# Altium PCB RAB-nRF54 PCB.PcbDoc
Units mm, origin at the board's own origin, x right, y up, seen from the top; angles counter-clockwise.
Board outline 50.3 x 82.73 mm, 2 copper layers (Top Layer, Bottom Layer), stack 1.622 mm thick; 96 components, 53 nets, 179 pads, 205 vias.
Unrouted connection lines stored in the file: 13.
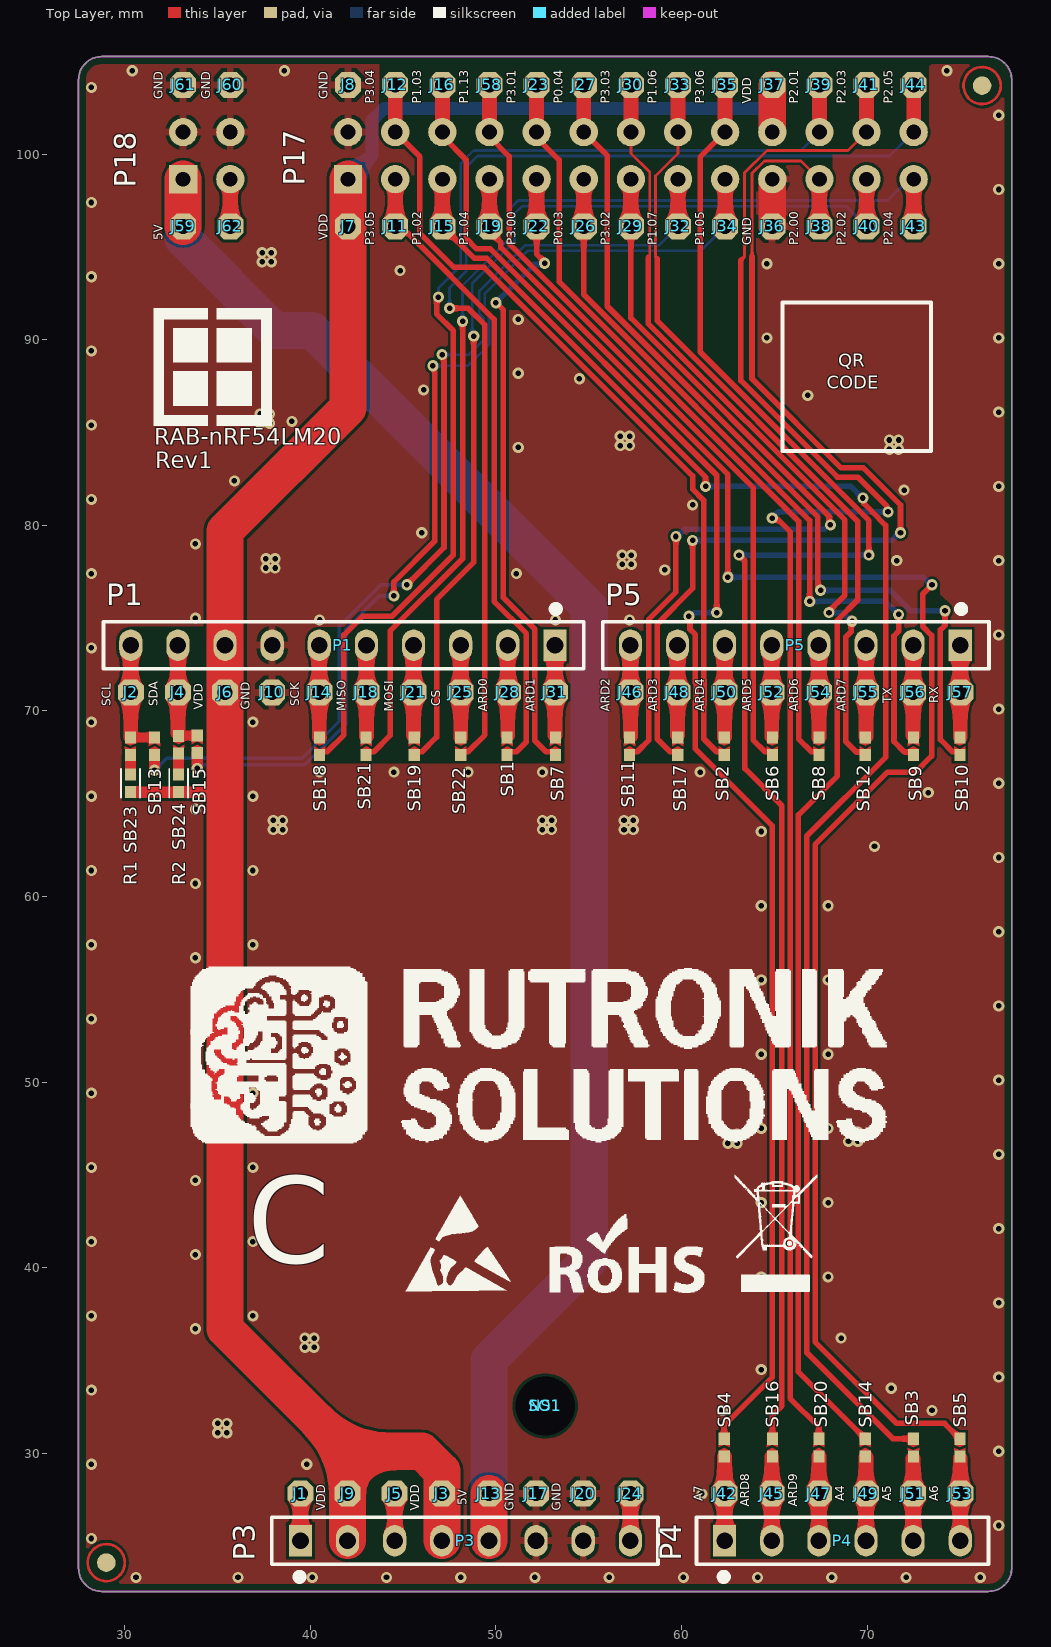
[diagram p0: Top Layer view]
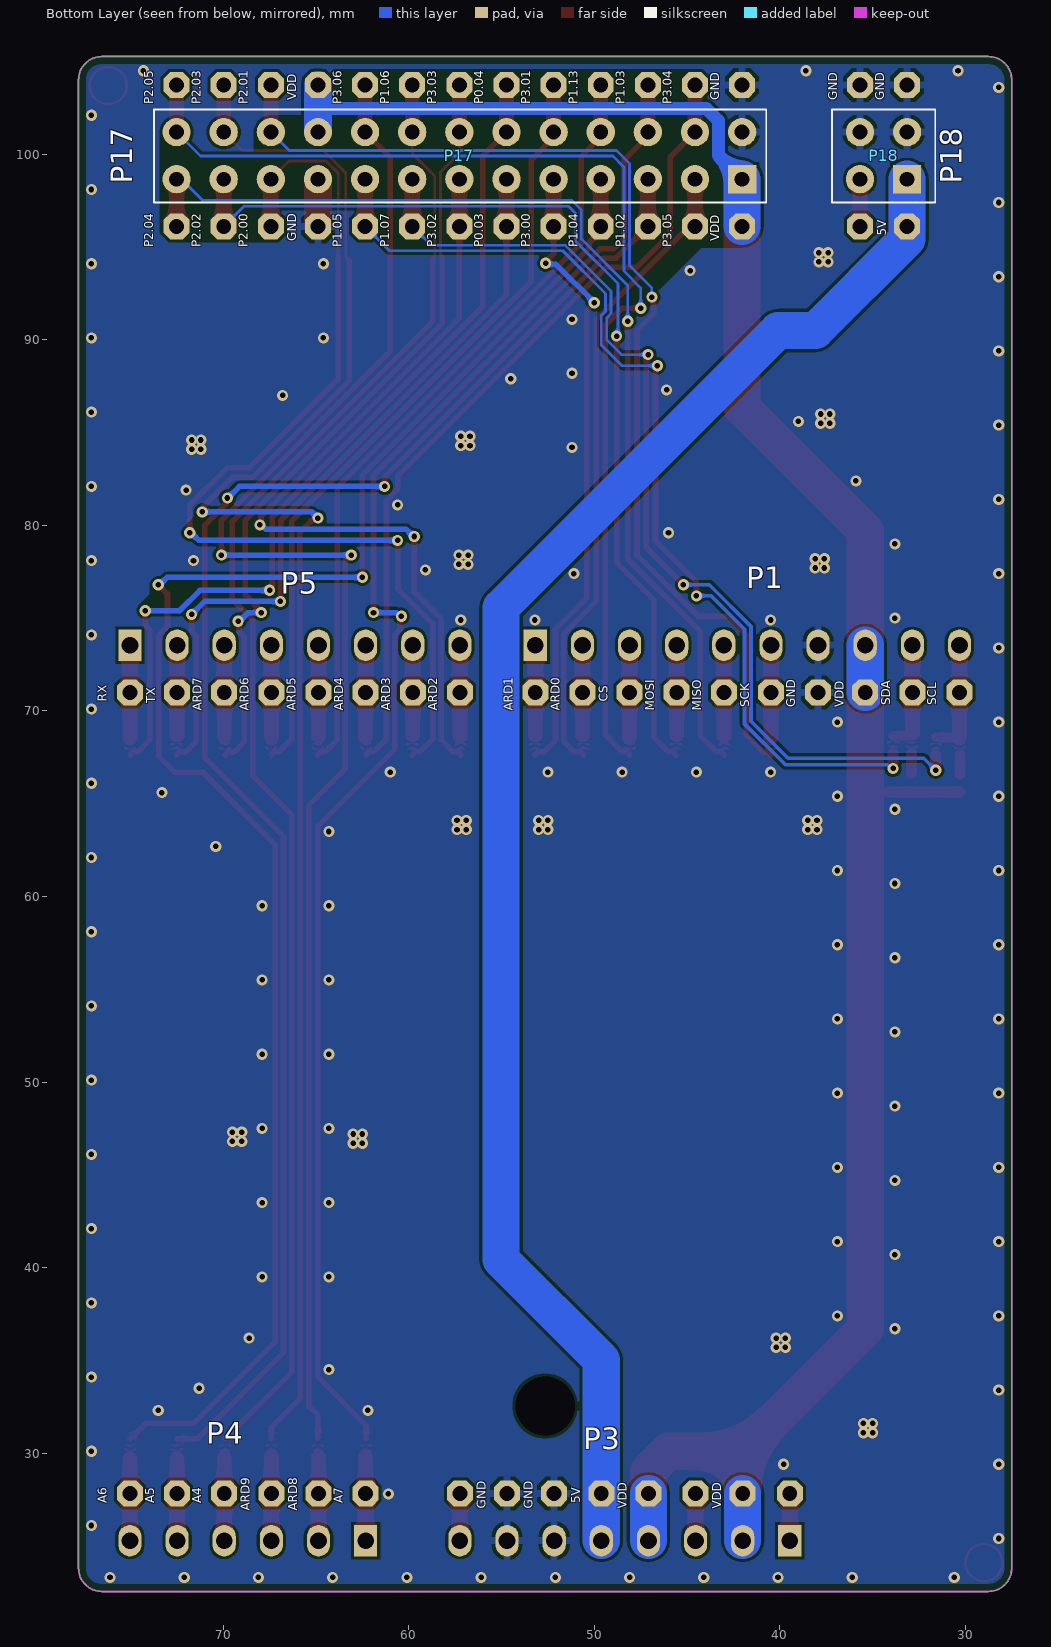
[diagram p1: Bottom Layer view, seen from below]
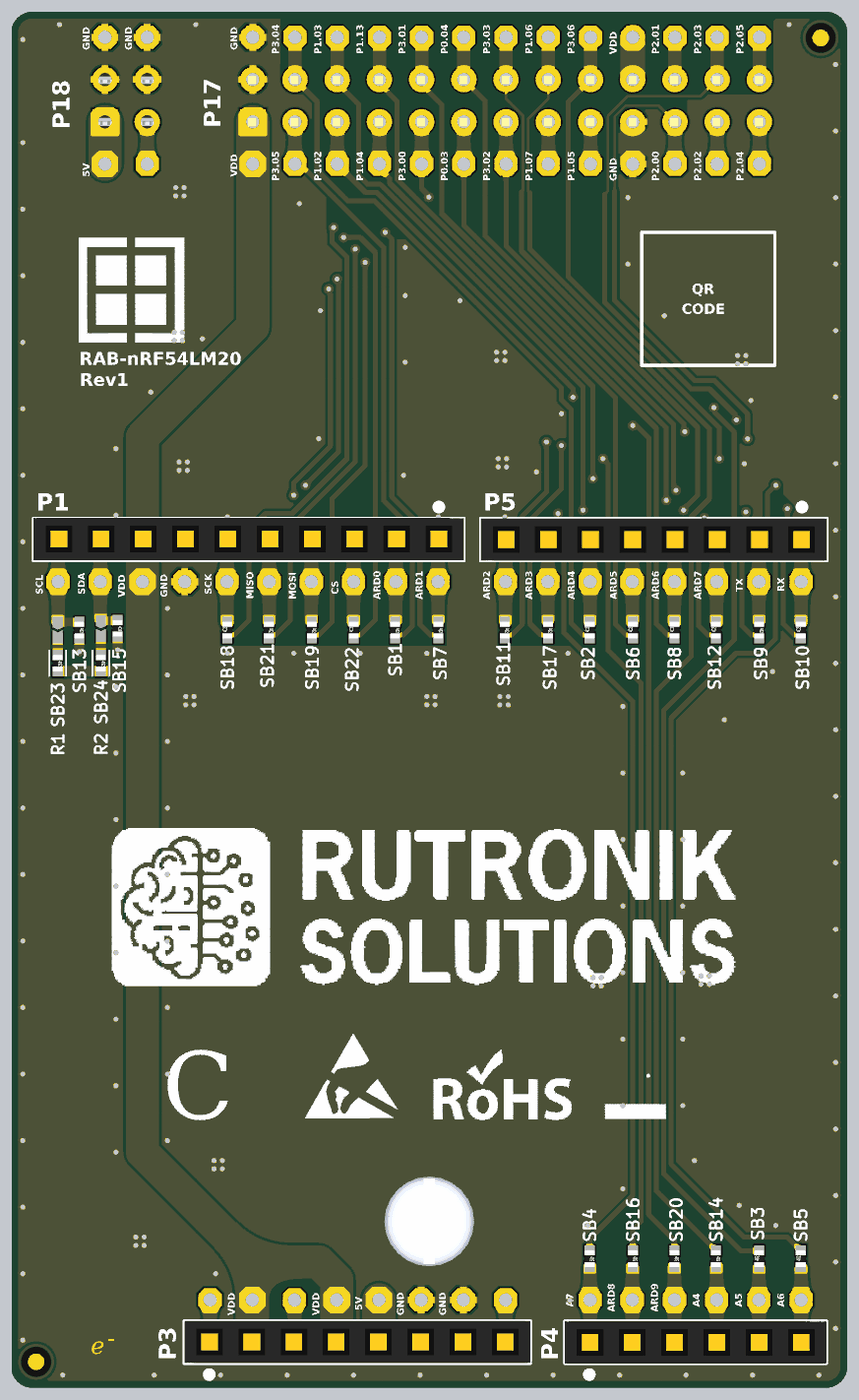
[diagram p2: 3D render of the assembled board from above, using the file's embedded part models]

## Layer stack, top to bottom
Top Solder: solder mask 0.01, Solder Resist, Dk 3.5
Top Layer: signal copper 0.036
Dielectric 1: dielectric 1.55, FR-4, Dk 4.2
Bottom Layer: signal copper 0.036
Bottom Solder: solder mask 0.01, Solder Resist, Dk 3.5

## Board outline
27.5,23.811 27.5,104 cw(c28.77,104) 28.77,105.27 76.53,105.27 cw(c76.53,104) 77.8,104 77.8,23.811 cw(c76.53,23.811) 76.53,22.541 28.77,22.541 cw(c28.77,23.811)

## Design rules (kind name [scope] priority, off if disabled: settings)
BoardOutlineClearance [All] p1: gap=0.4 ignorepadtopadclearanceinfootprint=FALSE
Clearance [All] p1: gap=0.15 ignorepadtopadclearanceinfootprint=FALSE
ComponentClearance "Schematic Component Clearance Constraint_1" [InComponent('NS1')] p1: gap=-1 collisioncheckmode=3 verticalgap=2540 showdistances=FALSE
ComponentClearance "Schematic Component Clearance Constraint" [InComponent('SO1')] p2: gap=-1 collisioncheckmode=3 verticalgap=2540 showdistances=FALSE
ComponentClearance [All] p3: gap=0.254 collisioncheckmode=3 verticalgap=0.254 showdistances=FALSE
HoleSize [All] p1: absolutevalues=TRUE maxlimit=12 minlimit=0.3 maxpercent=80.000 minpercent=20.000
HoleToHoleClearance [All] p1: gap=0.15 allowstackedmicrovias=TRUE
MinimumSolderMaskSliver [All] p1: minsoldermaskwidth=0
PolygonConnect [All] p1: thpad.connectstyle=Relief thpad.reliefconductorwidth=0.4 thpad.reliefentries=4 thpad.polygonreliefangle="90 Angle" thpad.airgapwidth=0.2 smdpad.connectstyle=Relief smdpad.reliefconductorwidth=0.4 smdpad.reliefentries=4 smdpad.polygonreliefangle="90 Angle" smdpad.airgapwidth=0.2 via.connectstyle=Direct via.reliefconductorwidth=0.254 via.reliefentries=4 via.polygonreliefangle="90 Angle" via.airgapwidth=0.254
RoutingVias [All] p1: holewidth=0.3 width=0.6 viastyle="Through Hole" minholewidth=0.3 minwidth=0.6 maxholewidth=0.3 maxwidth=0.6
SilkToSilkClearance [All] p1: silktosilkclearance=0
SilkToSolderMaskClearance [IsPad] p1: minsilkscreentomaskgap=0 clearancetoexposedcopper=TRUE
SolderMaskExpansion [All] p1: expansion=0.102 istentingtop=FALSE
SupplyNets "Schematic Supply Nets_4" [InNet('5V')] p1: voltage=0.000
SupplyNets "Schematic Supply Nets_2" [InNet('GND')] p2: voltage=0.000
SupplyNets "Schematic Supply Nets" [InNet('VDDIO')] p3: voltage=0.000
Width [All] p1: maxlimit=4 minlimit=0.15 preferedwidth=0.25
24 further rules are at their usual default settings.

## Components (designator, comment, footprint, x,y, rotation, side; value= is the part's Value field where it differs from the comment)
J1 "pin_tht" PIN_THT 39.463,27.821 r0 top
J2 "pin_tht" PIN_THT 30.319,71.001 r0 top
J3 "pin_tht" PIN_THT 47.083,27.821 r0 top
J4 "pin_tht" PIN_THT 32.859,71.001 r0 top
J5 "pin_tht" PIN_THT 44.543,27.821 r0 top
J6 "pin_tht" PIN_THT 35.399,71.001 r0 top
J7 "pin_tht" PIN_THT 42.032,96.114 r0 top
J8 "pin_tht" PIN_THT 42.032,103.734 r0 top
J9 "pin_tht" PIN_THT 42.003,27.821 r0 top
J10 "pin_tht" PIN_THT 37.939,71.001 r90 top
J11 "pin_tht" PIN_THT 44.572,96.114 r0 top
J12 "pin_tht" PIN_THT 44.572,103.734 r90 top
J13 "pin_tht" PIN_THT 49.623,27.821 r90 top
J14 "pin_tht" PIN_THT 40.479,71.001 r90 top
J15 "pin_tht" PIN_THT 47.112,96.114 r90 top
J16 "pin_tht" PIN_THT 47.112,103.734 r90 top
J17 "pin_tht" PIN_THT 52.163,27.821 r90 top
J18 "pin_tht" PIN_THT 43.019,71.001 r90 top
J19 "pin_tht" PIN_THT 49.652,96.114 r90 top
J20 "pin_tht" PIN_THT 54.703,27.821 r90 top
J21 "pin_tht" PIN_THT 45.559,71.001 r0 top
J22 "pin_tht" PIN_THT 52.192,96.114 r90 top
J23 "pin_tht" PIN_THT 52.192,103.734 r90 top
J24 "pin_tht" PIN_THT 57.243,27.821 r90 top
J25 "pin_tht" PIN_THT 48.099,71.001 r90 top
J26 "pin_tht" PIN_THT 54.732,96.114 r90 top
J27 "pin_tht" PIN_THT 54.732,103.734 r90 top
J28 "pin_tht" PIN_THT 50.639,71.001 r90 top
J29 "pin_tht" PIN_THT 57.272,96.114 r90 top
J30 "pin_tht" PIN_THT 57.272,103.734 r90 top
J31 "pin_tht" PIN_THT 53.179,71.001 r0 top
J32 "pin_tht" PIN_THT 59.812,96.114 r90 top
J33 "pin_tht" PIN_THT 59.812,103.734 r90 top
J34 "pin_tht" PIN_THT 62.352,96.114 r90 top
J35 "pin_tht" PIN_THT 62.352,103.734 r90 top
J36 "pin_tht" PIN_THT 64.892,96.114 r90 top
J37 "pin_tht" PIN_THT 64.892,103.734 r90 top
J38 "pin_tht" PIN_THT 67.432,96.114 r90 top
J39 "pin_tht" PIN_THT 67.432,103.734 r90 top
J40 "pin_tht" PIN_THT 69.972,96.114 r90 top
J41 "pin_tht" PIN_THT 69.972,103.734 r0 top
J42 "pin_tht" PIN_THT 62.323,27.821 r90 top
J43 "pin_tht" PIN_THT 72.512,96.114 r90 top
J44 "pin_tht" PIN_THT 72.512,103.734 r90 top
J45 "pin_tht" PIN_THT 64.863,27.821 r90 top
J46 "pin_tht" PIN_THT 57.243,71.001 r90 top
J47 "pin_tht" PIN_THT 67.403,27.821 r90 top
J48 "pin_tht" PIN_THT 59.783,71.001 r90 top
J49 "pin_tht" PIN_THT 69.943,27.821 r90 top
J50 "pin_tht" PIN_THT 62.323,71.001 r90 top
J51 "pin_tht" PIN_THT 72.483,27.821 r0 top
J52 "pin_tht" PIN_THT 64.863,71.001 r90 top
J53 "pin_tht" PIN_THT 75.023,27.821 r90 top
J54 "pin_tht" PIN_THT 67.403,71.001 r90 top
J55 "pin_tht" PIN_THT 69.943,71.001 r90 top
J56 "pin_tht" PIN_THT 72.483,71.001 r90 top
J57 "pin_tht" PIN_THT 75.023,71.001 r90 top
J58 "pin_tht" PIN_THT 49.652,103.734 r90 top
J59 "pin_tht" PIN_THT 33.142,96.114 r90 top
J60 "pin_tht" PIN_THT 35.682,103.734 r90 top
J61 "pin_tht" PIN_THT 33.142,103.734 r0 top
J62 "pin_tht" PIN_THT 35.682,96.114 r0 top
NS1 "NYLON_SCREW" 29311 52.65,32.541 r0 top value=P/N29341
P1 "DIGITAL 1" Arduino_HDR1X10_main 53.179,73.541 r180 top value=75915-310LF
P3 "POWER" rduino_HDR1X8_main 39.463,25.281 r0 top value=75915-308LF
P4 "ANALOG IN" Arduino_HDR1X6_main 62.323,25.281 r0 top value=75915-306LF
P5 "DIGITAL 2" rduino_HDR1X8_main 75.023,73.541 r180 top value=75915-308LF
P17 "Header 13X2" RECEPTACLE_2x13_2.54_5x8.5 42.032,101.194 r0 bottom value=87606-313LF
P18 "Header 2X2H" RECEPTACLE_2x2_2.54_5x8.5 33.142,101.194 r0 bottom value=87606-302LF
R1 "Res2" R0402 30.3,66.1 r270 top value=10K
R2 "Res2" R0402 32.9,66.1 r270 top value=10K
SB1 "Closed" SB_0402 50.6,68.1 r270 top value=0R
SB2 "Closed" SB_0402 62.3,68.1 r90 top value=0R
SB3 "Closed" SB_0402 72.5,30.3 r90 top value=0R
SB4 "Closed" SB_0402 62.3,30.3 r270 top value=0R
SB5 "Closed" SB_0402 75,30.3 r90 top value=0R
SB6 "Closed" SB_0402 64.9,68.1 r90 top value=0R
SB7 "Closed" SB_0402 53.2,68.1 r270 top value=0R
SB8 "Closed" SB_0402 67.4,68.1 r90 top value=0R
SB9 "Closed" SB_0402 72.5,68.1 r270 top value=0R
SB10 "Closed" SB_0402 75,68.1 r90 top value=0R
SB11 "Closed" SB_0402 57.2,68.1 r270 top value=0R
SB12 "Closed" SB_0402 69.9,68.1 r90 top value=0R
SB13 "Closed" SB_0402 31.6,68.1 r270 top value=0R
SB14 "Closed" SB_0402 69.9,30.3 r270 top value=0R
SB15 "Closed" SB_0402 33.9,68.2 r270 top value=0R
SB16 "Closed" SB_0402 64.9,30.3 r270 top value=0R
SB17 "Closed" SB_0402 59.8,68.1 r270 top value=0R
SB18 "Closed" SB_0402 40.5,68.1 r90 top value=0R
SB19 "Closed" SB_0402 45.6,68.1 r270 top value=0R
SB20 "Closed" SB_0402 67.4,30.3 r270 top value=0R
SB21 "Closed" SB_0402 43,68.1 r270 top value=0R
SB22 "Closed" SB_0402 48.1,68.1 r90 top value=0R
SB23 "Opened" "SB_0402 - open" 30.3,68.1 r90 top value=0R
SB24 "Opened" "SB_0402 - open" 32.9,68.175 r90 top value=0R
SO1 "STANDOFF" 24475 52.65,32.541 r0 top value=P/N25512

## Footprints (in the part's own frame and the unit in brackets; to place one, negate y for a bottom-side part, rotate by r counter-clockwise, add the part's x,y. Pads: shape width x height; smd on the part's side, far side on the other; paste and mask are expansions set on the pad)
24475 [mm] "5mm Hex Female Standoff P/N 24475"
  body extent -2.89,-2.5 2.89,2.5
29311 [mm] "M3 Pan Head screw, 6.0 L P/N 29311"
  body extent -2.7,-2.7 2.7,2.7, height 1.75
Arduino_HDR1X6_main [mm]
  rect 1.25x1.7 hole 0.9: 1(0,0)
  oval 1.25x1.7 hole 0.9: 2(2.54,0) 3(5.08,0) 4(7.62,0) 5(10.16,0) 6(12.7,0)
  silkscreen extent -1.51,-1.27 14.22,1.27, body extent -1.52,-1.27 14.22,1.27, height 8.6
Arduino_HDR1X10_main [mm]
  rect 1.25x1.7 hole 0.9: 1(0,0)
  oval 1.25x1.7 hole 0.9: 2(2.54,0) 3(5.08,0) 4(7.62,0) 5(10.16,0) 6(12.7,0) 7(15.24,0) 8(17.78,0) 9(20.32,0) 10(22.86,0)
  silkscreen extent -1.55,-1.27 24.33,1.27, body extent -1.57,-1.29 24.33,1.25, height 8.6
PIN_THT [mm]
  oct 1.4x1.4 hole 0.8: 1(0,0)
R0402 [mm]
  rect 0.65x0.6 smd: 1(-0.475,0) 2(0.475,0)
  silkscreen extent -0.76,-0.51 0.76,0.51, body extent -0.5,-0.3 0.5,0.3, height 0.2
rduino_HDR1X8_main [mm]
  rect 1.25x1.7 hole 0.9: 1(0,0)
  oval 1.25x1.7 hole 0.9: 2(2.54,0) 3(5.08,0) 4(7.62,0) 5(10.16,0) 6(12.7,0) 7(15.24,0) 8(17.78,0)
  silkscreen extent -1.55,-1.27 19.27,1.27, body extent -1.55,-1.26 19.27,1.28, height 8.6
RECEPTACLE_2x2_2.54_5x8.5 [mil]
  rect 60x60 hole 31.5: 1(0,100)
  round 60 hole 31.5: 2(0,0) 3(100,100) 4(100,0)
  silkscreen extent -60,-48 159,150, body extent -60,-48 160,149, height 335
RECEPTACLE_2x13_2.54_5x8.5 [mil]
  rect 60x60 hole 31.5: 1(0,100)
  round 60 hole 31.5: 2(0,0) 3(100,100) 4(100,0) 5(200,100) 6(200,0) 7(300,100) 8(300,0) 9(400,100) 10(400,0) 11(500,100) 12(500,0) 13(600,100) 14(600,0) 15(700,100) 16(700,0) 17(800,100) 18(800,0) 19(900,100) 20(900,0) 21(1000,100) 22(1000,0) 23(1100,100) 24(1100,0) 25(1200,100) 26(1200,0)
  silkscreen extent -51,-48 1248,150, body extent -51,-49 1249,151, height 331
SB_0402 [mm]
  rect 0.65x0.6 smd: 1(-0.475,0) 2(0.475,0)
  Top Layer region: -0.008,-0.3 -0.157,-0.3 -0.157,0.3 -0.008,0.3 -0.155,0
  Top Layer region: 0.164,-0.3 0.162,-0.3 0.015,0 0.162,0.3 0.164,0.3
  body extent -0.5,-0.3 0.5,0.3, height 0.2
"SB_0402 - open" [mm]
  rect 0.65x0.6 smd: 1(-0.475,0) 2(0.475,0)
  Top Layer region: -0.003,-0.3 -0.152,-0.3 -0.152,0.3 -0.003,0.3 -0.15,0
  Top Layer region: 0.169,-0.3 0.167,-0.3 0.02,0 0.167,0.3 0.169,0.3

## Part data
J1 J2 J3 J4 J5 J6 J7 J8 J9 J10 J11 J12 J13 J14 J15 J16 J17 J18 J19 J20 J21 J22 J23 J24 J25 J26 J27 J28 J29 J30 J31 J32 J33 J34 J35 J36 J37 J38 J39 J40 J41 J42 J43 J44 J45 J46 J47 J48 J49 J50 J51 J52 J53 J54 J55 J56 J57 J58 J59 J60 J61 J62: "Through-hole pin for wire connection."
NS1: "M3 Pan Head Machine Screw, 6.00L P/N 29341", Manufacturer="Keystone Electronics", Manufacturer Part No.="P/N 29341", Supplier part number=BAT4868
P1: library part "Header 10", Manufacturer="Amphenol ICC", Manufacturer Part No.=75915-310LF, Supplier part number=CONN7354
P3 P5: library part "Header 8", Manufacturer="Amphenol ICC", Manufacturer Part No.=75915-308LF, Supplier part number=CONN8727
P4: library part "Header 6", Manufacturer="Amphenol ICC", Manufacturer Part No.=75915-306LF, Supplier part number=CONN8726
P17: "Header, 13-Pin, Dual row", Manufacturer="Amphenol ICC", Manufacturer Part No.=87606-313LF, Supplier part number=CONN11183
P18: "Header, 2-Pin, Dual row, Right Angle", Manufacturer="Amphenol ICC", Manufacturer Part No.=87606-302LF, Supplier part number=CONN9239
R1 R2: Manufacturer=Yageo, Manufacturer Part No.=RC0402JR-1310KL, Supplier part number=WRC51147
SB1 SB2 SB3 SB4 SB5 SB6 SB7 SB8 SB9 SB10 SB11 SB12 SB13 SB14 SB15 SB16 SB17 SB18 SB19 SB20 SB21 SB22 SB23 SB24: library part "Circuit Breaker_close", "Circuit Breaker", Manufacturer=Yageo, Manufacturer Part No.=RC0402FR-070RL, Supplier part number=WRC53079
SO1: "5mm Hex Female Standoff P/N 25512", Manufacturer="Keystone Electronics", Manufacturer Part No.="P/N 25512", Supplier part number=BAT6084

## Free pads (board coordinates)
  round 1 smd paste-1 mask+0.4: ""(29,24.1) ""(76.2,103.7)
  round 0 hole 3.2: ""(52.65,32.541)

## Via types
v1: diameter 0.6, hole 0.3, Top Layer to Bottom Layer, tented both sides, 205 vias

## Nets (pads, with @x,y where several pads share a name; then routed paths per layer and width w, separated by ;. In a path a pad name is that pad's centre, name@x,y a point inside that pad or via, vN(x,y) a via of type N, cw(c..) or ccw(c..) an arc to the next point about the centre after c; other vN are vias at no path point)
5V: J13.1 J59.1 P3.5 P18.1 | length 90.9
  Top Layer w2: J59.1 P18.1 ; P3.5 J13.1
  Bottom Layer w2: P18.1 J59.1 33.142,95.436 38.078,90.5 40.1,90.5 55.029,75.571 55.029,40.429 49.623,35.023 J13.1 P3.5
AN_A4: J49.1 P4.4 SB14.2 | length 4.5
  Top Layer w0.8: P4.4 J49.1 SB14.2@69.943,29.782
AN_A5: J51.1 P4.5 SB3.1 | length 4.4
  Top Layer w0.8: P4.5 J51.1 SB3.1@72.483,29.715
AN_A6: J53.1 P4.6 SB5.1 | length 4.4
  Top Layer w0.8: P4.6 J53.1 SB5.1@75.023,29.713
AN_A7: J42.1 P4.1 SB4.2 | length 4.5
  Top Layer w0.8: P4.1 J42.1 SB4.2@62.323,29.802
ARD_IO0: J28.1 P1.2 SB1.1 | length 4.8
  Top Layer w0.8: SB1.1@50.639,68.696 J28.1 P1.2
ARD_IO1: J31.1 P1.1 SB7.1 | length 4.9
  Top Layer w0.8: SB7.1@53.179,68.686 J31.1 P1.1
ARD_IO2: J46.1 P5.8 SB11.1 | length 4.9
  Top Layer w0.8: SB11.1@57.243,68.646 J46.1 P5.8
ARD_IO3: J48.1 P5.7 SB17.1 | length 4.8
  Top Layer w0.8: SB17.1@59.783,68.7 J48.1 P5.7
ARD_IO4: J50.1 P5.6 SB2.2 | length 4.9
  Top Layer w0.8: SB2.2@62.323,68.598 J50.1 P5.6
ARD_IO5: J52.1 P5.5 SB6.2 | length 4.9
  Top Layer w0.8: SB6.2@64.863,68.612 J52.1 P5.5
ARD_IO6: J54.1 P5.4 SB8.2 | length 5
  Top Layer w0.8: SB8.2 67.403,68.578 J54.1 P5.4
ARD_IO7: J55.1 P5.3 SB12.2 | length 4.9
  Top Layer w0.8: SB12.2@69.943,68.618 J55.1 P5.3
ARD_IO8: J45.1 P4.2 SB16.2 | length 4.5
  Top Layer w0.8: P4.2 J45.1 SB16.2@64.863,29.788
ARD_IO9: J47.1 P4.3 SB20.2 | length 4.5
  Top Layer w0.8: SB20.2 67.403,29.822 J47.1 P4.3
GND: J8.1 J10.1 J17.1 J20.1 J36.1 J60.1 J61.1 P1.7 P3.6 P3.7 P17.2 P17.19 P18.2 P18.4 | length 2.7
  Top Layer w0.8: P17.2@42.032,101.043 P17.2
  Top Layer w1.5: J36.1 P17.19
  other v1: 30.6,23.3 36.1,23.3 40.1,23.3 44.1,23.3 48.1,23.3 52.1,23.3 56.1,23.3 60.1,23.3 64.1,23.3 68.1,23.3 72.1,23.3 76.1,23.3 28.2,25.4 77.1,26.1 61.1,27.8 28.2,29.4 39.8,29.4 77.1,30.1 35,31.1 35.5,31.1 35,31.6 35.5,31.6 62.2,32.3 73.5,32.3 28.2,33.4 71.3,33.5 77.1,34.1 64.3,34.5 39.7,35.7 40.2,35.7 39.7,36.2 40.2,36.2 68.6,36.2 33.8,36.7 28.2,37.4 36.9,37.4 77.1,38.1 64.3,39.5 67.9,39.5 33.8,40.7 28.2,41.4 36.9,41.4 77.1,42.1 64.3,43.5 67.9,43.5 33.8,44.7 28.2,45.4 36.9,45.4 77.1,46.1 62.5,46.7 63,46.7 69,46.8 69.5,46.8 62.5,47.2 63,47.2 69,47.3 69.5,47.3 64.3,47.5 67.9,47.5 33.8,48.7 28.2,49.4 36.9,49.4 77.1,50.1 64.3,51.5 67.9,51.5 33.8,52.7 28.2,53.4 36.9,53.4 77.1,54.1 64.3,55.5 67.9,55.5 33.8,56.7 28.2,57.4 36.9,57.4 77.1,58.1 64.3,59.5 67.9,59.5 33.8,60.7 28.2,61.4 36.9,61.4 77.1,62.1 70.4,62.7 64.3,63.5 38,63.6 38.5,63.6 52.5,63.6 53,63.6 56.9,63.6 57.4,63.6 38,64.1 38.5,64.1 52.5,64.1 53,64.1 56.9,64.1 57.4,64.1 33.8,64.7 28.2,65.4 36.9,65.4 73.3,65.6 77.1,66.1 40.5,66.7 44.5,66.7 48.5,66.7 52.5,66.7 61,66.7 28.2,69.4 36.9,69.4 77.1,70.1 28.2,73.4 77.1,74.1 40.5,74.9 53.2,74.9 57.2,74.9 33.8,75 28.2,77.4 51.1,77.4 59.1,77.6 37.6,77.7 38.1,77.7 56.8,77.9 57.3,77.9 71.6,78.1 77.1,78.1 37.6,78.2 38.1,78.2 56.8,78.4 57.3,78.4 33.8,79 46,79.6 60.6,81.1 28.2,81.4 72,81.9 77.1,82.1 35.9,82.4 71.2,84.1 71.7,84.1 51.2,84.2 56.7,84.3 57.2,84.3 71.2,84.6 71.7,84.6 56.7,84.8 57.2,84.8 28.2,85.4 37.3,85.5 37.8,85.5 39,85.6 37.3,86 37.8,86 77.1,86.1 66.8,87 46.1,87.3 54.5,87.9 51.2,88.2 28.2,89.4 64.6,90.1 77.1,90.1 51.2,91.1 28.2,93.4 44.838,93.732 64.6,94.1 77.1,94.1 37.4,94.2 37.9,94.2 37.4,94.7 37.9,94.7 28.2,97.4 77.1,98.1 77.1,102.1 28.2,103.6 30.4,104.5 38.6,104.5 74.3,104.5
I2C_SCL: J2.1 P1.10 SB13.1 SB23.2 | length 6.2
  Top Layer w0.5: SB23.2 SB13.1
  Top Layer w0.8: SB23.2@30.319,68.594 J2.1 P1.10
I2C_SDA: J4.1 P1.9 SB15.1 SB24.2 | length 5.7
  Top Layer w0.5: SB24.2 32.912,68.662 33.887,68.662 SB15.1
  Top Layer w0.8: SB24.2@32.859,68.816 J4.1 P1.9
NetJ1_1: J1.1 P3.1 | length 2.5
  Top Layer w0.8: P3.1 J1.1
NetJ5_1: J5.1 P3.3 | length 2.5
  Top Layer w0.8: P3.3 J5.1
NetJ24_1: J24.1 P3.8 | length 2.5
  Top Layer w0.8: P3.8 J24.1
NetJ62_1: J62.1 P18.3 | length 2.5
  Top Layer w0.8: J62.1 P18.3
NetR1_1: R1.1 SB23.1 | length 1
  Top Layer w0.6: R1.1@30.3,66.6 SB23.1
NetR2_1: R2.1 SB24.1 | length 1.1
  Top Layer w0.6: R2.1@32.9,66.65 SB24.1
P0.03: J26.1 P17.11 SB9.2 | length 41.2
  Top Layer w0.3: J26.1 54.732,92.441 66.9,80.273 66.9,75.913 v1(66.913,75.9) ; v1(71.7,75.2) 71.7,74.291 71.45,74.041 71.45,68.35 72,67.8 72.35,67.8 72.5,67.65 SB9.2
  Top Layer w0.8: J26.1 P17.11
  Bottom Layer w0.3: v1(66.913,75.9) 71,75.9 v1(71.7,75.2)
P0.04: J27.1 P17.12 SB10.1 | length 48.1
  Top Layer w0.3: P17.12 56,99.926 56,91.809 67.35,80.459 67.35,76.731 67.5,76.581 v1(67.5,76.5) ; v1(74.2,75.4) 74.2,74.617 73.95,74.367 73.95,68.45 74.6,67.8 74.85,67.8 75,67.65 SB10.1
  Top Layer w0.8: P17.12 J27.1
  Bottom Layer w0.3: v1(67.5,76.5) 71.249,76.5 72.349,75.4 v1(74.2,75.4)
P1.02: J15.1 P17.5 SB3.2 | length 87.6
  Top Layer w0.3: J15.1 48.826,94.4 49.5,94.4 61.3,82.6 v1(61.3,82.097) ; v1(69.776,81.476) 69.833,81.418 69.833,81.167 70.286,80.714 71,80 71,67.5 66.75,63.25 66.75,35.414 71.389,30.775 SB3.2
  Top Layer w0.8: J15.1 P17.5
  Bottom Layer w0.3: v1(61.3,82.097) 69.124,82.097 69.746,81.476 v1(69.776,81.476)
P1.03: J16.1 P17.6 SB4.1 | length 83.9
  Top Layer w0.3: P17.6 47.112,100.988 48.4,99.7 48.4,95.463 48.963,94.9 49.7,94.9 61.9,82.7 v1(61.9,75.3) ; v1(60.4,75.1) 60.457,75.043 60.457,74.4 60.75,74.108 60.75,71.509 60.783,71.476 60.783,70.527 60.75,70.494 60.75,67.95 64.9,63.8 64.9,34.1 62.3,31.5 SB4.1
  Top Layer w0.8: P17.6 J16.1
  Bottom Layer w0.3: v1(60.4,75.1) 60.481,75.1 60.681,75.3 v1(61.9,75.3)
P1.04: J19.1 P17.7 SB5.2 | length 92.6
  Top Layer w0.3: J19.1 49.652,95.852 50.264,95.24 50.264,94.972 62.5,82.736 v1(62.5,77.2) ; v1(73.5,76.8) 73,76.3 73,74.558 73.483,74.074 73.483,67.559 72.624,66.7 71.1,66.7 67.2,62.8 67.2,36 71.6,31.6 74.175,31.6 74.825,30.95 74.85,30.95 75,30.8 SB5.2
  Top Layer w0.8: J19.1 P17.7
  Bottom Layer w0.3: v1(62.5,77.2) 73.019,77.2 73.419,76.8 v1(73.5,76.8)
P1.05: J34.1 P17.17 SB15.2 | length 55
  Top Layer w0.3: v1(44.5,76.2) 44.5,76.949 46.7,79.149 46.7,88.288 46.657,88.33 46.657,88.543 v1(46.6,88.6)
  Top Layer w0.6: v1(33.9,66.9) SB15.2
  Top Layer w0.8: J34.1 P17.17
  Bottom Layer w0.15: v1(46.6,88.6) 48.5,88.6 49.625,89.725 49.625,91.315 49.4,91.54 49.4,92.5 51.7,94.8 61.038,94.8 J34.1
  Bottom Layer w0.2: v1(33.9,66.9) 34.008,66.9 34.208,67.1 39.7,67.1 41.9,69.3 41.9,74.405 43.695,76.2 v1(44.5,76.2)
P1.06: J33.1 P17.16 SB14.1 | length 80.8
  Top Layer w0.15: 58.7,94.37 58.6,94.47 58.6,98.838 59.812,100.05 P17.16
  Top Layer w0.3: 58.7,94.37 58.7,91.018 69.5,80.218 69.5,75.989 68.403,74.893 68.403,66.503 66.3,64.4 66.3,34.375 69.725,30.95 69.75,30.95 69.9,30.8 SB14.1
  Top Layer w0.8: P17.16 J33.1
P1.07: J32.1 P17.15 SB13.2 | length 54.8
  Top Layer w0.3: v1(45.2,76.8) 47.2,78.8 v1@47.2,89.2 ; v1(47.1,89.2) v1@47.157,89.143
  Top Layer w0.6: v1(31.6,66.8) SB13.2
  Top Layer w0.8: J32.1 P17.15
  Bottom Layer w0.15: v1(47.1,89.2) 48.542,89.2 49.325,89.983 49.325,91.191 49.1,91.416 49.1,92.624 51.576,95.1 58.798,95.1 J32.1
  Bottom Layer w0.2: v1(31.6,66.8) 32.25,67.45 39.555,67.45 41.55,69.445 41.55,74.55 43.8,76.8 v1(45.2,76.8)
P1.13: J58.1 P17.8 SB6.1 | length 42.6
  Top Layer w0.3: P17.8 49.652,100.948 50.714,99.886 50.714,95.186 63.863,82.037 63.863,68.437 64.5,67.8 64.75,67.8 64.9,67.65 SB6.1
  Top Layer w0.8: P17.8 J58.1
P2.00_A: J38.1 P17.21 SB17.2 | length 54.6
  Top Layer w0.15: 63.8,94.473 63.8,98.976 64.465,99.641 66.445,99.641 P17.21
  Top Layer w0.3: SB17.2 59.8,67.65 59.65,67.8 59.384,67.8 58.693,68.49 58.693,74.693 60.6,76.6 v1(60.6,79.192) ; 63.8,94.473 63.8,87.9 68.6,83.1 69.8,83.1 71.8,81.1 v1(71.8,79.6)
  Top Layer w0.8: J38.1 P17.21
  Bottom Layer w0.3: v1(60.6,79.192) 71.311,79.192 71.719,79.6 v1(71.8,79.6)
P2.01_A: J39.1 P17.22 SB18.1 | length 59.4
  Top Layer w0.3: SB18.1 40.5,67.65 40.65,67.8 40.9,67.8 41.8,68.7 41.8,74.1 42.8,75.1 44.4,75.1 47.7,78.4 47.7,90.5 46.8,91.4 46.8,92.2 v1(46.9,92.3)
  Top Layer w0.8: P17.22 J39.1
  Bottom Layer w0.15: v1(46.9,92.3) 46.9,92.8 48.1,94 48.1,99.5 48.8,100.2 66.438,100.2 P17.22
P2.02_A: J40.1 P17.23 SB19.2 | length 53.8
  Top Layer w0.3: SB19.2 45.6,67.65 45.75,67.8 46.016,67.8 46.8,68.584 46.8,76 48.8,78 v1(48.8,90.2)
  Top Layer w0.8: J40.1 P17.23
  Bottom Layer w0.15: v1(48.8,90.2) 48.725,90.275 48.725,93.025 51,95.3 51,96.8 51.4,97.2 68.886,97.2 J40.1
P2.03_A: J41.1 P17.24 SB20.1 | length 89.5
  Top Layer w0.15: 63.2,94.288 63.4,94.488 63.4,99 64.6,100.2 68.978,100.2 P17.24
  Top Layer w0.3: 63.2,94.288 63.2,87.8 68.4,82.6 69.5,82.6 71.071,81.029 71.071,80.786 v1(71.129,80.729) ; v1(64.892,80.392) 64.95,80.335 65.162,80.335 65.863,79.633 65.863,70.117 65.85,70.103 65.85,32.95 67.4,31.4 SB20.1
  Top Layer w0.8: P17.24 J41.1
  Bottom Layer w0.3: v1(64.892,80.392) 65.229,80.729 v1(71.129,80.729)
P2.04_A: J43.1 P17.25 SB21.2 | length 57.8
  Top Layer w0.3: SB21.2 43,67.65 43.15,67.8 43.416,67.8 44.3,68.684 44.3,74.3 48.2,78.2 v1(48.2,91)
  Top Layer w0.8: J43.1 P17.25
  Bottom Layer w0.15: v1(48.2,91) 48.2,92.924 50.7,95.424 50.7,97 51.2,97.5 71.1,97.5 72.254,98.654 P17.25
P2.05_A: J44.1 P17.26 SB22.1 | length 61.5
  Top Layer w0.3: v1(47.5,91.7) 48.5,91.7 49.4,90.8 49.4,68.7 48.5,67.8 48.25,67.8 48.1,67.65 SB22.1
  Top Layer w0.8: P17.26 J44.1
  Bottom Layer w0.15: v1(47.5,91.7) 47.5,92.8 48.4,93.7 48.4,99.3 49,99.9 71.218,99.9 P17.26
P3.00: J22.1 P17.9 SB7.2 | length 34.1
  Top Layer w0.3: v1(50,92) 50.4,91.6 50.4,76.1 52.089,74.411 52.089,68.411 52.7,67.8 53.05,67.8 53.2,67.65 SB7.2 ; J22.1 52.196,96.11 52.196,94.634 52.624,94.205 v1(52.624,94.124)
  Top Layer w0.8: J22.1 P17.9
  Bottom Layer w0.3: v1(50,92) 52.067,94.067 52.567,94.067 v1(52.624,94.124)
P3.01: J23.1 P17.10 SB8.1 | length 42.6
  Top Layer w0.3: P17.10 52.192,100.908 53.4,99.7 53.4,93.136 66.313,80.223 66.313,68.487 67,67.8 67.25,67.8 67.4,67.65 SB8.1
  Top Layer w0.8: P17.10 J23.1
P3.02: J29.1 P17.13 SB11.2 | length 44.6
  Top Layer w0.3: SB11.2 57.2,67.65 57.35,67.8 57.616,67.8 58.243,68.427 58.243,74.943 59.7,76.4 v1(59.7,79.4) ; J29.1 57.272,91.173 67.964,80.482 67.964,80.079 v1(68.021,80.021)
  Top Layer w0.8: J29.1 P17.13
  Bottom Layer w0.3: v1(59.7,79.4) 59.764,79.4 60.156,79.792 67.711,79.792 67.94,80.021 v1(68.021,80.021)
P3.03: J30.1 P17.14 SB12.1 | length 43.1
  Top Layer w0.15: P17.14 57.272,100.05 58.289,99.033 58.289,94.524 58.2,94.435
  Top Layer w0.3: 58.2,94.435 58.2,90.882 68.8,80.282 68.8,76.231 67.95,75.381 v1(67.95,75.3) ; v1(69.195,74.835) 69.137,74.778 69.137,74.268 68.853,73.984 68.853,68.347 69.4,67.8 69.75,67.8 69.9,67.65 SB12.1
  Top Layer w0.8: P17.14 J30.1
  Bottom Layer w0.3: v1(67.95,75.3) 68.649,75.3 69.113,74.835 v1(69.195,74.835)
P3.04: J12.1 P17.4 SB2.1 | length 44.6
  Top Layer w0.3: P17.4 45.9,99.866 45.9,95.736 47.736,93.9 49.364,93.9 60.6,82.664 60.6,81.949 61.2,81.349 61.2,71.695 61.233,71.662 61.233,70.341 61.2,70.307 61.2,68.5 61.9,67.8 62.15,67.8 62.3,67.65 SB2.1
  Top Layer w0.8: P17.4 J12.1
P3.05: J11.1 P17.3 SB1.2 | length 34.8
  Top Layer w0.3: J11.1 44.834,96.114 45.221,95.728 45.272,95.728 49.9,91.1 49.9,75.9 51.639,74.161 51.639,68.339 51.1,67.8 50.75,67.8 50.6,67.65 SB1.2
  Top Layer w0.8: J11.1 P17.3
P3.06: J35.1 P17.18 SB16.1 | length 85.4
  Top Layer w0.3: P17.18 61,99.842 61,89.355 70.1,80.255 v1(70.1,78.4) ; v1(63.1,78.4) 63.413,78.087 63.413,66.887 65.4,64.9 65.4,32.55 64.9,32.05 SB16.1@64.9,30.8
  Top Layer w0.8: P17.18 J35.1
  Bottom Layer w0.3: v1(63.1,78.4) v1(70.1,78.4)
SPI_CS: J25.1 P1.3 SB22.2 | length 5
  Top Layer w0.8: SB22.2 J25.1 P1.3
SPI_MISO: J18.1 P1.5 SB21.1 | length 4.9
  Top Layer w0.8: SB21.1@43.019,68.651 J18.1 P1.5
SPI_MOSI: J21.1 P1.4 SB19.1 | length 4.8
  Top Layer w0.8: SB19.1@45.559,68.691 J21.1 P1.4
SPI_SCK: J14.1 P1.6 SB18.2 | length 5
  Top Layer w0.8: P1.6 J14.1 40.479,68.596 SB18.2
UART_RX: J57.1 P5.1 SB10.2 | length 4.9
  Top Layer w0.8: SB10.2@75.023,68.598 J57.1 P5.1
UART_TX: J56.1 P5.2 SB9.1 | length 4.9
  Top Layer w0.8: SB9.1@72.483,68.685 J56.1 P5.2
VDDIO: J3.1 J6.1 J7.1 J9.1 J37.1 P1.8 P3.2 P3.4 P17.1 P17.20 R1.2 R2.2 | length 134
  Top Layer w0.6: R1.2 R2.2 35.375,65.625 35.4,65.6
  Top Layer w1.5: P17.20 J37.1
  Top Layer w2: J6.1 P1.8 ; J6.1 35.4,65.6 35.4,36.703 42.003,30.1 ; P1.8 35.4,79.7 42.032,86.332 J7.1 P17.1 ; P3.2 J9.1 42.003,30.1 ; P3.4 J3.1 47.083,29.028 46.012,30.1 42.003,30.1
  Bottom Layer w0.7: P17.1 43.31,99.932 43.31,101.81 43.964,102.464 64.892,102.464
  Bottom Layer w1.5: P17.20 64.892,102.464 J37.1
  Bottom Layer w2: J6.1 P1.8 ; P3.2 J9.1 ; J7.1 P17.1 ; P3.4 J3.1
copper on no net: | length 12.6
  Top Layer w0.15: 30,24.1 ccw(c29,24.1) 30,24.1 ; 77.2,103.7 ccw(c76.2,103.7) 77.2,103.7

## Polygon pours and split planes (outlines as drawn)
GND on Top Layer "TOP_GND" (solid, remove dead copper, pour order 0): 27.5,23.811 ccw(c28.77,23.811) 28.77,22.541 76.53,22.541 ccw(c76.53,23.811) 77.8,23.811 77.8,104 ccw(c76.53,104) 76.53,105.27 28.77,105.27 ccw(c28.77,104) 27.5,104
GND on Bottom Layer "BOT_GND" (solid, remove dead copper, pour order 1): 27.5,23.811 ccw(c28.77,23.811) 28.77,22.541 76.53,22.541 ccw(c76.53,23.811) 77.8,23.811 77.8,104 ccw(c76.53,104) 76.53,105.27 28.77,105.27 ccw(c28.77,104) 27.5,104

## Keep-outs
Keep-Out Layer:
  lines w0.1: 27.5,23.811 ccw(c28.77,23.811) 28.77,22.541 76.53,22.541 ccw(c76.53,23.811) 77.8,23.811 77.8,104 ; 27.5,23.811 27.5,23.811 ; 27.5,23.811 27.5,104 cw(c28.77,104) 28.77,105.27 76.53,105.27 cw(c76.53,104) 77.8,104 ; 77.8,104 77.8,104

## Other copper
Top Layer:
  pour cut-out: 46.45,92.39 46.45,94.45 46.5,94.5 48.5,92.5 48.5,92.4
  pour cut-out: 67.432,98.654 67.602,98.654 68.162,99.214 68.162,100.464 67.432,101.194
  pour cut-out: 50.4,91.6 52.3,91.6 51.9,92 50,92
  pour cut-out: 73.95,76.89 73.95,76.286 74.581,75.655 74.327,75.4 73.029,75.4 73,75.429 73.5,75.929 73.5,76.8
  pour cut-out: 57.65,67.15 63.25,67.15 63.4,67.3 62.975,67.725 57.275,67.725
  pour cut-out: 40.479,74.548 42.013,74.548 43.019,73.541 40.479,73.541
  pour cut-out: 30.319,74.548 34.393,74.548 35.399,73.541 30.319,73.541
  pour cut-out: 43.722,104.159 43.7,104.181 43.7,105 73.3,105 73.4,104.9 73.362,104.862 73.362,103.309 73.362,100.842 73.192,100.842 72.632,100.282 44.452,100.282 43.66,101.074
  pour cut-out: 40.95,67.15 53.65,67.15 53.697,67.197 53.697,68.472 41.247,68.472 41.04,68.679
  pour cut-out: 42.003,24.121 47.083,24.121 47.083,25.281 42.003,25.281
  pour cut-out: 63.098,24.281 63.105,24.275 75.023,24.275 75.023,25.281 62.323,25.281
Bottom Layer:
  pour cut-out: 68.344,101.074 68.344,99.944 68.3,99.9 66.9,99.9 66.9,100.662 67.432,101.194
  pour cut-out: 62.352,98.654 63.598,99.9 66.186,99.9 67.432,98.654 67.4,98.622 67.4,97.5 62.3,97.5
  pour cut-out: 67.552,102.106 67.546,102.1 65,102.1 64.892,101.992 64.892,101.194 67.432,101.194
  pour cut-out: 44.997,104.584 64.042,104.584 64.892,103.734 64.892,102.464 45.842,102.464 44.572,103.734
  pour cut-out: 69.547,95.264 72.937,95.264 73.424,95.751 73.424,101.314 72.632,101.314 69.972,98.654
  pour cut-out: 67.857,95.264 69.547,95.264 69.972,95.689 69.972,96.114 67.432,96.114
  pour cut-out: 42.032,94.954 44.246,94.954 46.9,92.3 47.112,92.512 47.112,96.114 42.032,96.114
  pour cut-out: 66.463,75.99 66.463,77.063 66.7,77.3 67.5,76.5
  pour cut-out: 73.95,76.71 73.95,76.286 74.455,75.781 74.173,75.5 73.8,75.5 73.8,76.5 73.5,76.8
  pour cut-out: 71.579,80.818 71.579,80.458 72.181,79.855 71.927,79.6 71.8,79.6 71.129,80.271 71.129,80.729

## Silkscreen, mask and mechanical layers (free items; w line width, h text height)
Top Overlay:
  drawing of 53 lines, arcs and shapes, not listed
  text "GND" at 32.214,102.974 h0.8 r90
  text "GND" at 34.754,102.974 h0.8 r90
  text "GND" at 41.104,102.974 h0.8 r90
  text "P3.04" at 43.6,102.72 h0.8 r90
  text "P1.03" at 46.14,102.72 h0.8 r90
  text "P1.13" at 48.68,102.72 h0.8 r90
  text "P3.01" at 51.22,102.72 h0.8 r90
  text "P0.04" at 53.76,102.72 h0.8 r90
  text "P3.03" at 56.3,102.72 h0.8 r90
  text "P1.06" at 58.84,102.72 h0.8 r90
  text "P3.06" at 61.38,102.72 h0.8 r90
  text "VDD" at 63.92,102.72 h0.8 r90
  text "P2.01" at 66.46,102.72 h0.8 r90
  text "P2.03" at 69,102.72 h0.8 r90
  text "P2.05" at 71.54,102.72 h0.8 r90
  text "P17" at 40.1,98.3 h2 r90
  text "P18" at 31,98.2 h2 r90
  text "5V" at 32.214,95.354 h0.8 r90
  text "VDD" at 41.104,95.354 h0.8 r90
  text "P3.05" at 43.6,95.1 h0.8 r90
  text "P1.02" at 46.14,95.1 h0.8 r90
  text "P1.04" at 48.68,95.1 h0.8 r90
  text "P3.00" at 51.22,95.1 h0.8 r90
  text "P0.03" at 53.76,95.1 h0.8 r90
  text "P3.02" at 56.3,95.1 h0.8 r90
  text "P1.07" at 58.84,95.1 h0.8 r90
  text "P1.05" at 61.38,95.1 h0.8 r90
  text "GND" at 63.92,95.1 h0.8 r90
  text "P2.00" at 66.46,95.1 h0.8 r90
  text "P2.02" at 69,95.1 h0.8 r90
  text "P2.04" at 71.54,95.1 h0.8 r90
  text "QR" at 68.44,88.31 h1.2
  text "CODE" at 67.84,87.11 h1.2
  text "RAB-nRF54LM20" at 31.597,84.045 h1.5
  text "Rev1" at 31.627,82.775 h1.5
  text "P1" at 29,75.3 h2
  text "P5" at 55.9,75.3 h2
  text "TX" at 71.5,70.4 h0.8 r90
  text "RX" at 74,70.4 h0.8 r90
  text "SCL" at 29.391,70.241 h0.8 r90
  text "SDA" at 31.931,70.241 h0.8 r90
  text "SCK" at 39.551,70.241 h0.8 r90
  text "CS" at 47.171,70.241 h0.8 r90
  text "VDD" at 34.347,70.071 h0.8 r90
  text "GND" at 36.887,70.071 h0.8 r90
  text "MISO" at 42.061,69.971 h0.8 r90
  text "MOSI" at 44.621,69.941 h0.8 r90
  text "ARD0" at 49.701,69.941 h0.8 r90
  text "ARD1" at 52.241,69.941 h0.8 r90
  text "ARD2" at 56.305,69.941 h0.8 r90
  text "ARD3" at 58.845,69.941 h0.8 r90
  text "ARD4" at 61.385,69.941 h0.8 r90
  text "ARD5" at 63.925,69.941 h0.8 r90
  text "ARD6" at 66.465,69.941 h0.8 r90
  text "ARD7" at 69.005,69.941 h0.8 r90
  text "C" at 36.596,38.707 h8
  text "A7" at 61.3,27.4 h0.8 r90
  text "A4" at 68.92,27.4 h0.8 r90
  text "A5" at 71.46,27.4 h0.8 r90
  text "A6" at 74,27.4 h0.8 r90
  text "5V" at 48.6,27.2 h0.8 r90
  text "ARD8" at 63.8,27.1 h0.8 r90
  text "ARD9" at 66.4,27.1 h0.8 r90
  text "VDD" at 40.951,26.891 h0.8 r90
  text "VDD" at 46.031,26.891 h0.8 r90
  text "GND" at 51.111,26.891 h0.8 r90
  text "GND" at 53.651,26.891 h0.8 r90
  text "P3" at 37.4,24.2 h2 r90
  text "P4" at 60.4,24.2 h2 r90
Bottom Overlay:
  text "GND" at 34.21,102.9 h0.8 r270
  text "GND" at 36.75,102.9 h0.8 r270
  text "GND" at 43.1,102.9 h0.8 r270
  text "VDD" at 65.9,102.9 h0.8 r270
  text "P3.04" at 45.66,102.7 h0.8 r270
  text "P1.03" at 48.2,102.7 h0.8 r270
  text "P1.13" at 50.74,102.7 h0.8 r270
  text "P3.01" at 53.28,102.7 h0.8 r270
  text "P0.04" at 55.82,102.7 h0.8 r270
  text "P3.03" at 58.36,102.7 h0.8 r270
  text "P1.06" at 60.9,102.7 h0.8 r270
  text "P3.06" at 63.44,102.7 h0.8 r270
  text "P2.01" at 68.52,102.7 h0.8 r270
  text "P2.03" at 71.06,102.7 h0.8 r270
  text "P2.05" at 73.6,102.7 h0.8 r270
  text "P18" at 29.8,98.4 h2 r270
  text "P17" at 74.5,98.4 h2 r270
  text "5V" at 34.1,95.6 h0.8 r270
  text "VDD" at 43.1,95.3 h0.8 r270
  text "GND" at 65.9,95.3 h0.8 r270
  text "P3.05" at 45.66,95 h0.8 r270
  text "P1.02" at 48.2,95 h0.8 r270
  text "P1.04" at 50.74,95 h0.8 r270
  text "P3.00" at 53.28,95 h0.8 r270
  text "P0.03" at 55.82,95 h0.8 r270
  text "P3.02" at 58.36,95 h0.8 r270
  text "P1.07" at 60.9,95 h0.8 r270
  text "P1.05" at 63.44,95 h0.8 r270
  text "P2.00" at 68.52,95 h0.8 r270
  text "P2.02" at 71.06,95 h0.8 r270
  text "P2.04" at 73.6,95 h0.8 r270
  text "P1" at 41.8,76.2 h2
  text "P5" at 66.9,75.9 h2
  text "CS" at 49.1,70.5 h0.8 r270
  text "RX" at 76.1,70.5 h0.8 r270
  text "TX" at 73.5,70.4 h0.8 r270
  text "SCL" at 31.4,70.3 h0.8 r270
  text "SDA" at 33.9,70.3 h0.8 r270
  text "VDD" at 36.4,70.2 h0.8 r270
  text "GND" at 39,70.2 h0.8 r270
  text "SCK" at 41.5,70.2 h0.8 r270
  text "MISO" at 44.076,70 h0.8 r270
  text "MOSI" at 46.616,70 h0.8 r270
  text "ARD0" at 51.696,70 h0.8 r270
  text "ARD1" at 54.236,70 h0.8 r270
  text "ARD2" at 58.3,70 h0.8 r270
  text "ARD3" at 60.84,70 h0.8 r270
  text "ARD4" at 63.38,70 h0.8 r270
  text "ARD5" at 65.92,70 h0.8 r270
  text "ARD6" at 68.46,70 h0.8 r270
  text "ARD7" at 71,70 h0.8 r270
  text "P4" at 70.9,30.1 h2
  text "P3" at 50.6,29.8 h2
  text "5V" at 50.6,27.3 h0.8 r270
  text "A7" at 63.4,27.3 h0.8 r270
  text "A4" at 71.02,27.3 h0.8 r270
  text "A5" at 73.56,27.3 h0.8 r270
  text "A6" at 76.1,27.3 h0.8 r270
  text "VDD" at 43,27 h0.8 r270
  text "VDD" at 48.08,27 h0.8 r270
  text "GND" at 53.16,27 h0.8 r270
  text "GND" at 55.7,27 h0.8 r270
  text "ARD8" at 65.86,26.9 h0.8 r270
  text "ARD9" at 68.4,26.9 h0.8 r270
Top Solder:
  text "-" at 33.285,25.032 h2
  text "e" at 32.284,24.582 h2
Mechanical 1:
  lines w0.1: 32.642,97.384 33.642,97.384 ; 32.642,102.464 33.642,102.464 ; 33.142,96.884 33.142,97.884 ; 33.142,97.384 33.142,102.464 ; 33.142,98.654 33.142,101.194 ; 33.142,101.964 33.142,102.964 ; 35.182,97.384 36.182,97.384 ; 35.182,102.464 36.182,102.464 ; 35.682,96.884 35.682,97.884 ; 35.682,101.964 35.682,102.964 ; 38.963,25.281 39.963,25.281 ; 39.463,24.781 39.463,25.781 ; 41.532,97.384 42.532,97.384 ; 41.532,102.464 42.532,102.464 ; 42.032,96.884 42.032,97.884 ; 42.032,97.384 42.032,102.464 ; 42.032,98.654 42.032,101.194 ; 42.032,101.964 42.032,102.964 ; 52.679,73.541 53.679,73.541 ; 53.179,73.041 53.179,74.041 ; 61.823,25.281 62.823,25.281 ; 62.323,24.781 62.323,25.781 ; 72.012,97.384 73.012,97.384 ; 72.012,102.464 73.012,102.464 ; 72.512,96.884 72.512,97.884 ; 72.512,101.964 72.512,102.964 ; 74.523,73.541 75.523,73.541 ; 75.023,73.041 75.023,74.041 ; 29.049,72.271 29.049,74.811 54.449,74.811 54.449,72.271 29.049,72.271 ; 38.193,24.011 58.513,24.011 58.513,26.551 38.193,26.551 38.193,24.011 ; 55.973,72.271 76.293,72.271 76.293,74.811 55.973,74.811 55.973,72.271 ; 61.053,24.011 76.293,24.011 76.293,26.551 61.053,26.551 61.053,24.011
Mechanical 13:
  lines w0.1: 30.319,71.001 30.319,73.541 ; 32.859,71.001 32.859,73.541 ; 33.142,96.114 33.142,98.654 ; 33.142,101.194 33.142,103.734 ; 35.399,71.001 35.399,73.541 ; 35.682,96.114 35.682,98.654 ; 35.682,101.194 35.682,103.734 ; 37.939,71.001 37.939,73.541 ; 39.463,25.281 39.463,27.821 ; 40.479,71.001 40.479,73.541 ; 42.003,25.281 42.003,27.821 ; 42.032,96.114 42.032,98.654 ; 42.032,101.194 42.032,103.734 ; 43.019,71.001 43.019,73.541 ; 44.543,25.281 44.543,27.821 ; 44.572,96.114 44.572,98.654 ; 44.572,101.194 44.572,103.734 ; 45.559,71.001 45.559,73.541 ; 47.083,25.281 47.083,27.821 ; 47.112,96.114 47.112,98.654 ; 47.112,101.194 47.112,103.734 ; 48.099,71.001 48.099,73.541 ; 49.623,25.281 49.623,27.821 ; 49.652,96.114 49.652,98.654 ; 49.652,101.194 49.652,103.734 ; 50.639,71.001 50.639,73.541 ; 52.163,25.281 52.163,27.821 ; 52.192,96.114 52.192,98.654 ; 52.192,101.194 52.192,103.734 ; 53.179,71.001 53.179,73.541 ; 54.703,25.281 54.703,27.821 ; 54.732,96.114 54.732,98.654 ; 54.732,101.194 54.732,103.734 ; 57.243,25.281 57.243,27.821 ; 57.243,71.001 57.243,73.541 ; 57.272,96.114 57.272,98.654 ; 57.272,101.194 57.272,103.734 ; 59.783,71.001 59.783,73.541 ; 59.812,96.114 59.812,98.654 ; 59.812,101.194 59.812,103.734 ; 62.323,25.281 62.323,27.821 ; 62.323,71.001 62.323,73.541 ; 62.352,96.114 62.352,98.654 ; 62.352,101.194 62.352,103.734 ; 64.863,25.281 64.863,27.821 ; 64.863,71.001 64.863,73.541 ; 64.892,96.114 64.892,98.654 ; 64.892,101.194 64.892,103.734 ; 67.403,25.281 67.403,27.821 ; 67.403,71.001 67.403,73.541 ; 67.432,96.114 67.432,98.654 ; 67.432,101.194 67.432,103.734 ; 69.943,25.281 69.943,27.821 ; 69.943,71.001 69.943,73.541 ; 69.972,96.114 69.972,98.654 ; 69.972,101.194 69.972,103.734 ; 72.483,25.281 72.483,27.821 ; 72.483,71.001 72.483,73.541 ; 72.512,96.114 72.512,98.654 ; 72.512,101.194 72.512,103.734 ; 75.023,25.281 75.023,27.821 ; 75.023,71.001 75.023,73.541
